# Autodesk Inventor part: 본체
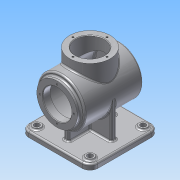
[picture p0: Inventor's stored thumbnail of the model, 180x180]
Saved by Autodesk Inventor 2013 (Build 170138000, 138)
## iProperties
Created: 2015-07
Part Number: 본체
Material: 알루미늄 6061
Document SubType Name: Modeling
Designer: Administrator
Density: 2.71 g/cm^3
Mass: 1277.74 g
Surface Area: 1267.64 cm^2
Volume: 471.49 cm^3
Author: Administrator
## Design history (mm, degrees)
sketch "스케치1"
  geometry: C1 r 45 at (0, 0); 1 further point
  constraints: 1 centre point, 1 coincident
  dimensions: "d0" = 90 diameter of C1
extrude "돌출1" new body sketch "스케치1" stored distance "d1" = 110; taper "d2" = 0 deg
sketch "스케치2"
  geometry: C1 r 38 at (0, 0); 1 further point
  constraints: 1 centre point, 1 coincident
  dimensions: "d3" = 76 diameter of C1
extrude "돌출2" join sketch "스케치2" distance "d4" = 7; taper "d5" = 0 deg
sketch "스케치3"
  geometry: C1 r 38 at (0, 0); 1 further point
  constraints: 1 centre point, 1 coincident
  dimensions: "d6" = 76 diameter of C1
extrude "돌출3" join sketch "스케치3" distance "d7" = 62; taper "d8" = 0 deg
node "작업 평면1"
sketch "스케치4"
  geometry: L1 (-65, 65)-(65, 65); L2 (65, 65)-(65, -65); L3 (65, -65)-(-65, -65); L4 (-65, -65)-(-65, 65); 3 further points
  constraints: 8 end point, 2 midpoint, 2 parallel, 2 perpendicular, 1 horizontal, 1 horizontal alignment, 1 vertical alignment
  dimensions: "d10" = 130 distance of L1.start L1.end
extrude "돌출4" join sketch "스케치4" distance "d12" = 10; taper "d13" = 0 deg
sketch "스케치5"
  geometry: L1 (-68, 45)-(22, 45); L2 (22, 45)-(22, -45); L3 (22, -45)-(-68, -45); L4 (-68, -45)-(-68, 45); L5 (-68, -65)-(-68, 65) reference; 2 further points
  constraints: 8 end point, 2 midpoint, 2 parallel, 2 perpendicular, 1 horizontal
  dimensions: "d16" = 90 distance of L3.end L1.start
extrude "돌출5" join sketch "스케치5" stored distance "d18" = 10; taper "d19" = 0 deg
sketch "스케치6"
  geometry: L1 (65, -68)-(-65, -68) reference; L2 (45, 0)-(45, -68); L3 (45, -68)-(-45, -68); L4 (-45, -68)-(-45, 0); L5 (-45, 0)-(45, 0); A1 r 45 centre (0, 0) between (-45, 0) and (45, 0) reference; 2 further points
  constraints: 8 end point, 2 midpoint, 2 point on circle, 2 tangent, 1 parallel, 1 perpendicular
  dimensions: "d23" = 90 distance of L2.end L3.end
extrude "돌출6" join sketch "스케치6" stored distance "d25" = 10; taper "d26" = 0 deg
fillet "모깎기1" dims "d27" = 15
sketch "스케치7"
  geometry: L1 (50, 65)-(-50, 65) reference; L2 (65, -50)-(65, 50) reference; L3 (-50, -65)-(50, -65) reference; L4 (-65, 50)-(-65, -50) reference; C1 r 7.5 at (-50, 50); C2 r 7.5 at (50, 50); C3 r 7.5 at (-50, -50); C4 r 7.5 at (50, -50); A1 r 15 centre (-50, 50) between (-50, 65) and (-65, 50) reference; A2 r 15 centre (-50, 50) between (-50, 65) and (-65, 50) reference; A3 r 15 centre (50, 50) between (65, 50) and (50, 65) reference; A4 r 15 centre (50, -50) between (50, -65) and (65, -50) reference; A5 r 15 centre (-50, -50) between (-65, -50) and (-50, -65) reference; 1 further point
  constraints: 4 centre point, 4 coincident, 3 equal radius
  dimensions: "d28" = 15 diameter of C1
extrude "돌출7" join sketch "스케치7" distance "d30" = 3; taper "d31" = 0 deg
hole "구멍1" diameter "d34" = 10; stored, may be unused: countersink angle "d38" = 90 deg, drill point angle "d40" = 118 deg; dims "d32" = 10, "d33" = 10, "d35" = 6, "d36" = 4, "d37" = 2, "d39" = 8
hole "구멍2" diameter "d43" = 10; stored, may be unused: countersink angle "d47" = 90 deg, drill point angle "d49" = 118 deg; dims "d41" = 10, "d42" = 10, "d44" = 6, "d45" = 4, "d46" = 2, "d48" = 8
hole "구멍3" diameter "d52" = 10; stored, may be unused: countersink angle "d56" = 90 deg, drill point angle "d58" = 118 deg; dims "d50" = 10, "d51" = 10, "d53" = 6, "d54" = 4, "d55" = 2, "d57" = 8
hole "구멍4" diameter "d61" = 10; stored, may be unused: countersink angle "d65" = 90 deg, drill point angle "d67" = 118 deg; dims "d59" = 10, "d60" = 10, "d62" = 6, "d63" = 4, "d64" = 2, "d66" = 8
sketch "스케치8"
  geometry: L1 (0, 48)-(40, 48); L2 (40, 48)-(40, -48); L3 (40, -48)-(0, -48); L4 (-45, -55)-(45, -55) reference; L5 (-45, -55)-(-45, 55) reference; L6 (45, -55)-(45, 55) reference; L7 (0, 48)-(0, -48); 1 further point
  constraints: 8 end point, 2 parallel, 1 horizontal, 1 perpendicular, 1 vertical alignment
  dimensions: "d68" = 7 distance between parallel lines of L4 L3; "d70" = 96 distance of L1.end L2.end; "d71" = 80 diameter of L2 L7
revolve "회전1" sketch "스케치8" stored, may be unused: angle "d72" = 90 deg
hole "구멍5" diameter "d75" = 54; stored, may be unused: countersink angle "d79" = 90 deg, drill point angle "d81" = 0 deg; dims "d73" = 10, "d74" = 10, "d76" = 6, "d77" = 4, "d78" = 2, "d80" = 14
hole "구멍6" diameter "d84" = 54; stored, may be unused: countersink angle "d88" = 90 deg, drill point angle "d90" = 0 deg; dims "d82" = 10, "d83" = 10, "d85" = 6, "d86" = 4, "d87" = 2, "d89" = 50
sketch "스케치9"
  geometry: L1 (-24.887, 3.602)-(24.887, 3.602); L2 (24.887, 3.602)-(24.887, -3.602); L3 (24.887, -3.602)-(-24.887, -3.602); L4 (-24.887, -3.602)-(-24.887, 3.602); 3 further points
  constraints: 2 midpoint, 1 horizontal, 1 horizontal alignment, 1 vertical alignment, 2 other
  dimensions: "d91" = 49.77477 distance between parallel lines of L2 L4; "d92" = 7.20489 distance between parallel lines of L1 L3
feature "엠보싱1" sketch "스케치9" dims "d93" = 0.5, "d94" = 0
sketch "스케치10"
  geometry: 2 further points
  constraints: 1 vertical alignment
  dimensions: "d98" = 32 distance of point (0, 32) point (0, 0)
hole "구멍7" sketch "스케치10" at (0, 32) diameter "d99" = 3.242; stored, may be unused: countersink angle "d103" = 90 deg, drill point angle "d105" = 118 deg; dims "d100" = 8, "d101" = 4, "d102" = 2, "d104" = 10
sketch "스케치11"
  geometry: 2 further points
  constraints: 1 vertical alignment
  dimensions: "d109" = 32 distance of point (0, 32) point (0, 0)
hole "구멍8" sketch "스케치11" at (0, 32) diameter "d110" = 3.242; stored, may be unused: countersink angle "d114" = 90 deg, drill point angle "d116" = 118 deg; dims "d111" = 8, "d112" = 4, "d113" = 2, "d115" = 10
chamfer "모따기1" distance "d95" = 1; stored, may be unused: second distance "d96" = 2, angle "d97" = 45 deg
fillet "모깎기2" dims "d120" = 3
fillet "모깎기3" dims "d121" = 3
fillet "모깎기4" dims "d122" = 3
fillet "모깎기5" dims "d123" = 3
node "솔리드1"
pattern_circular "원형 패턴1" dims angle "d107" = 360 deg
pattern_circular "원형 패턴2" dims angle "d118" = 360 deg
node "투영된 루프1"
node "투영된 루프2"
other parameters: "d9" = -78
